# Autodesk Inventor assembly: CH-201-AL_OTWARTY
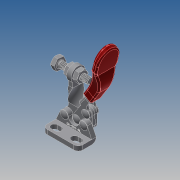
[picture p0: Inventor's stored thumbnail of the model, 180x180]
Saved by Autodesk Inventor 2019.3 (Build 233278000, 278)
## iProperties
Company: ·L?¤¤?
Created: 2010-06
Part Number: CH-201-AL_OTWARTY
Material: Ogólny
Description: STEP AP203
Document SubType Name: Assembly
Designer: CADENGINEERING4
Sending System: SolidWorks 2005179
Preprocessor: SwSTEP 2.0
Title: CH-201-AL.STEP
Author: ·L?¥Î?
Revision Number: ANY
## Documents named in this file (8)
- E:\STRONA\Horizontal toggle clamp\CH-201-AL\CH-201-AL_OTWARTY.iam
- E:\STRONA\Horizontal toggle clamp\CH-201-AL\201-AL-01___.ipt
- E:\STRONA\Horizontal toggle clamp\CH-201-AL\M4___.ipt
- E:\STRONA\Horizontal toggle clamp\CH-201-AL\201-A-02___.ipt
- E:\STRONA\Horizontal toggle clamp\CH-201-AL\201-06___.ipt
- E:\STRONA\Horizontal toggle clamp\CH-201-AL\CH-SA-042007___.ipt
- E:\STRONA\Horizontal toggle clamp\CH-201-AL\201-A-04___.ipt
- E:\STRONA\Horizontal toggle clamp\CH-201-AL\201-03___.iam
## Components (12 placed, 12 different names)
1. 201-AL-01_??_1 — Zestawiające:8, Zestawiające:9, Zestawiające:13, Zestawiające:14, Zestawiające:15, Zestawiające:16, Przejściowe:1
2. M4_??_2 — Równoległe:1, Zestawiające:2, Zestawiające:4
3. 201-A-02_??_3 — Zestawiające:1, Zestawiające:2, Zestawiające:3, Zestawiające:21, Zestawiające:22, Zestawiające:23
4. 201-06_??_4 — Zestawiające:17, Zestawiające:18, Zestawiające:19
5. CH-SA-042007_??_5 — Równoległe:1, Zestawiające:1, Zestawiające:4, Zestawiające:5
6. M4_??_6 — Zestawiające:3, Zestawiające:5
7. 201-06_??_7 — Zestawiające:6, Zestawiające:7, Zestawiające:22
8. 201-06_??_8 — Zestawiające:8, Zestawiające:9, Zestawiające:23
9. 201-06_??_9 — Zestawiające:15, Zestawiające:16
10. 201-A-04_??_10 — Zestawiające:10, Zestawiające:11, Zestawiające:12, Zestawiające:13, Zestawiające:17, Zestawiające:20
11. 201-03_??_11 [sub-assembly] — Zestawiające:6, Zestawiające:7, Zestawiające:18, Zestawiające:19, Zestawiające:20, Zestawiające:21, Przejściowe:1
12. 201-A-04_??_12 — Zestawiające:10, Zestawiające:11, Zestawiające:12, Zestawiające:14
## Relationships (25: Mate 23, Flush 1, Transitional 1)
- Równoległe:1 [Flush]: M4_??_2 ↔ CH-SA-042007_??_5
- Zestawiające:1 [Mate]: 201-A-02_??_3 ↔ CH-SA-042007_??_5
- Zestawiające:2 [Mate]: M4_??_2 ↔ 201-A-02_??_3
- Zestawiające:3 [Mate]: 201-A-02_??_3 ↔ M4_??_6
- Zestawiające:4 [Mate]: M4_??_2 ↔ CH-SA-042007_??_5
- Zestawiające:5 [Mate]: CH-SA-042007_??_5 ↔ M4_??_6
- Zestawiające:6 [Mate]: 201-06_??_7 ↔ 201-03_??_11
- Zestawiające:7 [Mate]: 201-06_??_7 ↔ 201-03_??_11
- Zestawiające:8 [Mate]: 201-AL-01_??_1 ↔ 201-06_??_8
- Zestawiające:9 [Mate]: 201-AL-01_??_1 ↔ 201-06_??_8
- Zestawiające:10 [Mate]: 201-A-04_??_10 ↔ 201-A-04_??_12
- Zestawiające:11 [Mate]: 201-A-04_??_10 ↔ 201-A-04_??_12
- Zestawiające:12 [Mate]: 201-A-04_??_10 ↔ 201-A-04_??_12
- Zestawiające:13 [Mate]: 201-AL-01_??_1 ↔ 201-A-04_??_10
- Zestawiające:14 [Mate]: 201-AL-01_??_1 ↔ 201-A-04_??_12
- Zestawiające:15 [Mate]: 201-AL-01_??_1 ↔ 201-06_??_9
- Zestawiające:16 [Mate]: 201-AL-01_??_1 ↔ 201-06_??_9
- Zestawiające:17 [Mate]: 201-06_??_4 ↔ 201-A-04_??_10
- Zestawiające:18 [Mate]: 201-06_??_4 ↔ 201-03_??_11
- Zestawiające:19 [Mate]: 201-06_??_4 ↔ 201-03_??_11
- Zestawiające:20 [Mate]: 201-A-04_??_10 ↔ 201-03_??_11
- Zestawiające:21 [Mate]: 201-A-02_??_3 ↔ 201-03_??_11
- Zestawiające:22 [Mate]: 201-A-02_??_3 ↔ 201-06_??_7
- Zestawiające:23 [Mate]: 201-A-02_??_3 ↔ 201-06_??_8
- Przejściowe:1 [Transitional]: 201-AL-01_??_1 ↔ 201-03_??_11
